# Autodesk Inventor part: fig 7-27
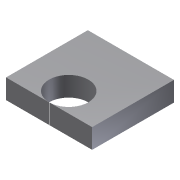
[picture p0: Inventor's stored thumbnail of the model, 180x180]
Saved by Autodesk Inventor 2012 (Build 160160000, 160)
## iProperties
Created: 2005-04
Part Number: fig 7-27
Document SubType Name: Modeling
Designer: CADCIM
Density: 1 g/cm^3
Material: Default
Author: CADCIM
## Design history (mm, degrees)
sketch "Sketch1"
  geometry: L1 (9.851, -16.047)-(9.851, -1.297); L2 (9.851, -1.297)-(-12.082, -1.297); L3 (-12.082, -1.297)-(-12.082, -16.047); L4 (-12.082, -16.047)-(9.851, -16.047)
  constraints: 8 end point, 2 parallel, 1 perpendicular, 1 vertical
extrude "Extrusion1" new body sketch "Sketch1" distance "d0" = 5; taper "d1" = 0 deg
sketch "Sketch2"
  geometry: C1 r 5 at (-1.115, -17.135); 1 further point
  constraints: 1 centre point
  dimensions: "d7" = 10.96654 horizontal distance of point (-12.082, -16.047) C1.centre; "d8" = 10 diameter of C1
extrude "Extrusion2" cut sketch "Sketch2" stored distance "d2" = 5; taper "d3" = 0 deg
feature "Move Face3" dims "d9" = 6.088
body "Solid1"
